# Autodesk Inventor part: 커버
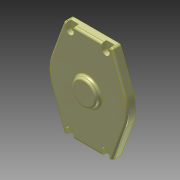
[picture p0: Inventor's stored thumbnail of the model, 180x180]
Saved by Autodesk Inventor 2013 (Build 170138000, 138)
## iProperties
Created: 2023-11
Part Number: 커버
Material: 알루미늄 6061
Document SubType Name: Modeling
Designer: mdu-01
Density: 1 g/cm^3
Author: mdu-01
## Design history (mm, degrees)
sketch "스케치1"
  geometry: L1 (-34.498, 66.026)-(-51.683, 18.811) reference; L2 (31.679, 68)-(-31.679, 68) reference; L3 (51.683, 18.811)-(34.498, 66.026) reference; L4 (-51.683, -18.811)-(-34.498, -66.026) reference; L5 (34.498, -66.026)-(51.683, -18.811) reference; L6 (-31.679, -68)-(31.679, -68) reference; C1 r 10 at (0, 0) reference; A1 r 3 centre (-31.679, 65) between (-31.679, 68) and (-34.498, 66.026) reference; A2 r 3 centre (31.679, 65) between (34.498, 66.026) and (31.679, 68) reference; A3 r 55 centre (0, 0) between (51.683, -18.811) and (51.683, 18.811) reference; A4 r 55 centre (0, 0) between (-51.683, 18.811) and (-51.683, -18.811) reference; A5 r 3 centre (-31.679, -65) between (-34.498, -66.026) and (-31.679, -68) reference; A6 r 3 centre (31.679, -65) between (31.679, -68) and (34.498, -66.026) reference; 1 further point
extrude "돌출1" new body sketch "스케치1" distance "d0" = 12; taper "d1" = 0 deg
sketch "스케치2"
  geometry: C1 r 10 at (0, 0) reference; 1 further point
extrude "돌출2" cut sketch "스케치2" distance "d2" = 10; taper "d3" = 0 deg
sketch "스케치3"
  geometry: C1 r 17.5 at (0, 0); 1 further point
  constraints: 1 centre point, 1 coincident
  dimensions: "d4" = 35 diameter of C1
extrude "돌출3" join sketch "스케치3" distance "d5" = 6; taper "d6" = 0 deg
fillet "모깎기1" dims "d7" = 3
sketch "스케치4"
  geometry: L1 (25, -61)-(-25, -61); L2 (-25, -61)-(-25, 61); L3 (-25, 61)-(25, 61); L4 (25, 61)-(25, -61); L5 (25, -61)-(-25, 61); L6 (-25, -61)-(25, 61); C1 r 2.458 at (-25, 61) reference; 1 further point
  constraints: 12 end point, 2 midpoint, 2 parallel, 1 coincident, 1 horizontal, 1 perpendicular
hole "구멍1" sketch "스케치4" at (-25, 61), (25, 61), (-25, -61), (25, -61) diameter "d8" = 6.6; stored, may be unused: countersink angle "d12" = 90 deg, drill point angle "d14" = 118 deg; dims "d9" = 6, "d10" = 11, "d11" = 6.6, "d13" = 8
sketch "스케치5"
  geometry: L1 (-30.5, 61)-(-19.5, 61); L2 (-19.5, 61)-(-19.5, 68); L3 (-19.5, 68)-(-30.5, 68); L4 (-30.5, 68)-(-30.5, 61); L5 (31.679, 68)-(-31.679, 68) reference; L6 (0, 0)-(0, 68); L7 (0, 0)-(-55, 0); L8 (19.5, 61)-(19.5, 68); L9 (19.5, 68)-(30.5, 68); L10 (30.5, 68)-(30.5, 61); L11 (30.5, 61)-(19.5, 61); L12 (19.5, -61)-(19.5, -68); L13 (19.5, -68)-(30.5, -68); L14 (30.5, -68)-(30.5, -61); L15 (30.5, -61)-(19.5, -61); L16 (-30.5, -68)-(-30.5, -61); L17 (-19.5, -68)-(-30.5, -68); L18 (-19.5, -61)-(-19.5, -68); L19 (-30.5, -61)-(-19.5, -61); A1 r 5.5 centre (-25, 61) between (-28.775, 65) and (-21.225, 65) reference; A2 r 55 centre (0, 0) between (-51.683, 18.811) and (-51.683, -18.811) reference
  constraints: 36 end point, 12 symmetric about line, 2 parallel, 2 point on circle, 2 tangent, 1 collinear, 1 horizontal, 1 midpoint, 1 perpendicular
extrude "돌출4" cut sketch "스케치5" stored distance "d15" = 6; taper "d16" = 0 deg
sketch "스케치6"
  geometry: L1 (10, 10)-(-10, 10) reference; L2 (7, 9.5)-(7, 2.044) reference; L3 (0, 10)-(0, 14.041); L4 (0, 14.041)-(7, 10); 1 further point
  constraints: 6 end point, 2 point on line, 1 midpoint, 1 parallel, 1 vertical, 2 other
  dimensions: "d17" = 60 deg angle of L3 L4
revolve "회전1" sketch "스케치6" stored, may be unused: angle "d18" = 90 deg
node "솔리드1"
node "참조1"
node "참조2"
node "참조3"
node "참조4"
node "참조5"
node "참조6"
node "참조7"
node "참조8"
node "참조9"
node "참조10"
node "참조11"
node "참조12"
node "참조13"
node "참조14"
